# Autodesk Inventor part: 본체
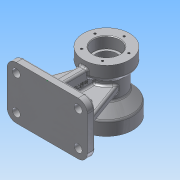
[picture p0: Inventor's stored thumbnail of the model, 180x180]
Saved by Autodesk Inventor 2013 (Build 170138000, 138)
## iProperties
Created: 2015-08
Part Number: 본체
Material: 알루미늄 6061
Document SubType Name: Modeling
Designer: WINDOWS7
Density: 2.71 g/cm^3
Mass: 1062.91 g
Surface Area: 749.728 cm^2
Volume: 392.217 cm^3
Author: WINDOWS7
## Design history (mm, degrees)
sketch "스케치1"
  geometry: 1 further point
sketch "스케치2"
  geometry: C1 r 26 at (0, 90); 1 further point
  constraints: 1 centre point, 1 vertical alignment
  dimensions: "d0" = 52 diameter of C1; "d2" = 90 distance of C1.centre point (0, 0)
extrude "돌출1" new body sketch "스케치2" distance "d3" = 90; taper "d4" = 0 deg
sketch "스케치3"
  geometry: C1 r 26 at (0, 0) reference; C2 r 35 at (0, 0); 1 further point
  constraints: 1 centre point, 1 coincident
  dimensions: "d5" = 70 diameter of C2
extrude "돌출2" join sketch "스케치3" distance "d7" = 20; taper "d8" = 0 deg
sketch "스케치4"
  geometry: C1 r 26 at (0, 0) reference; C2 r 40 at (0, 0); 1 further point
  constraints: 1 centre point, 1 coincident
  dimensions: "d9" = 80 diameter of C2
extrude "돌출3" join sketch "스케치4" distance "d11" = 20; taper "d12" = 0 deg
sketch "스케치5"
  geometry: L1 (125, 0)-(125, -20) reference; L2 (116, -20)-(116, -70) reference; L3 (130, -90)-(130, -70) reference; L4 (55, 0)-(55, -20) reference; L5 (64, -20)-(64, -70) reference; L6 (55, 0)-(125, 0) reference; L7 (64, -20)-(116, -20) reference; L8 (116, -70)-(64, -70) reference; L9 (130, -90)-(50, -90) reference; L10 (90, 0)-(90, -90); L11 (125, -20)-(116, -25.196); L12 (130, -70)-(116, -53.315); L13 (116, -25.196)-(116, -20); L14 (116, -53.315)-(116, -70); 1 further point
  constraints: 10 end point, 2 midpoint, 2 point on line, 1 collinear, 1 parallel
  dimensions: "d13" = 60 deg angle of L2 L11; "d14" = 40 deg angle of L2 L12
revolve "회전1" sketch "스케치5" stored, may be unused: angle "d15" = 90 deg
sketch "스케치6"
  geometry: L1 (61, 0.744)-(-61, 0.744); L2 (-61, 0.744)-(-61, -79.256); L3 (-61, -79.256)-(61, -79.256); L4 (61, -79.256)-(61, 0.744); L5 (26, -25.196)-(26, -53.315) reference; L6 (-26, -25.196)-(-26, -53.315) reference; L7 (-35, 0)-(35, 0) reference; 4 further points
  constraints: 8 end point, 3 midpoint, 2 parallel, 1 horizontal, 1 horizontal alignment, 1 perpendicular, 1 vertical alignment
  dimensions: "d16" = 80 distance of L3.end L1.start; "d18" = 122 distance of L2.end L3.end
extrude "돌출4" join sketch "스케치6" distance "d19" = 12; taper "d20" = 0 deg
node "작업 평면1"
sketch "스케치7"
  geometry: L1 (122, 0)-(0, 0) reference; L2 (0, 0)-(0, 12) reference; L3 (122, 12)-(0, 12) reference; L4 (122, 0)-(122, 12) reference; L5 (10, 12)-(37.488, 87.523); L6 (37.488, 87.523)-(84.512, 87.523); L7 (84.512, 87.523)-(112, 12); 1 further point
  constraints: 6 end point, 2 point on line, 1 perpendicular
  dimensions: "d22" = 10 distance of L3.start L7.end; "d23" = 70 deg angle of L3 L7; "d24" = 10 distance of L2.end L5.start; "d25" = 70 deg angle of L3 L5; "d26" = 47.02406 distance of L5.end L6.end
extrude "돌출5" join sketch "스케치7" stored distance "d27" = 12; taper "d28" = 0 deg
node "작업 평면2"
sketch "스케치8"
  geometry: L1 (80, 12)-(0, 12) reference; L2 (80, 0)-(0, 0) reference; L3 (0, 0)-(0, 12) reference; L4 (80, 12)-(0, 12) reference; L5 (80, 0)-(80, 12) reference; L6 (10, 83.257)-(10, 12); L7 (10, 83.257)-(82.565, 83.257); L8 (82.565, 83.257)-(70, 12); 1 further point
  constraints: 6 end point, 2 perpendicular, 2 point on line, 1 parallel
  dimensions: "d30" = 10 distance of L8.end L1.start; "d31" = 80 deg angle of L1 L8; "d32" = 10 distance of L1.end L6.end; "d33" = 72.5645 distance of L6.start L7.end
extrude "돌출6" join sketch "스케치8" stored distance "d34" = 12; taper "d35" = 0 deg
sketch "스케치9"
  geometry: L1 (79, 42)-(91, 42); L2 (91, 42)-(91, 24); L3 (91, 24)-(79, 24); L4 (79, 24)-(79, 42); A1 r 6 centre (85, 36) between (91, 36) and (79, 36); A2 r 6 centre (85, 30) between (79, 30) and (91, 30); 1 further point
  constraints: 8 end point, 5 point on circle, 4 point on line, 2 centre point, 2 parallel, 2 tangent, 1 equal radius, 1 horizontal, 1 perpendicular, 1 vertical alignment
  dimensions: "d36" = 12 distance of L1.start L1.end; "d38" = 18 distance of L3.end L1.start; "d39" = 12 diameter of A1; "d40" = 24 horizontal distance of point (61, 0) A2.centre; "d41" = 30 vertical distance of point (61, 0) A2.centre
extrude "돌출7" cut sketch "스케치9" distance "d42" = 12; taper "d43" = 0 deg
sketch "스케치10"
  geometry: C1 r 20 at (0, 90); A1 r 35 centre (0, 90) between (0, 125) and (35, 90) reference; 1 further point
  constraints: 1 centre point, 1 coincident
  dimensions: "d44" = 40 diameter of C1
extrude "돌출8" cut sketch "스케치10" distance "d46" = 17; taper "d47" = 0 deg
sketch "스케치11"
  geometry: C1 r 26 at (0, 90); A1 r 40 centre (0, 90) between (0, 130) and (40, 90) reference; 1 further point
  constraints: 1 centre point, 1 coincident
  dimensions: "d48" = 52 diameter of C1
extrude "돌출9" cut sketch "스케치11" distance "d50" = 20; taper "d51" = 0 deg
sketch "스케치12"
  geometry: L1 (6, -39.547)-(6, -25.298) reference; L2 (-6, -25.298)-(-6, -39.547) reference; C1 r 19 at (0, 0); A1 r 26 centre (0, 0) between (6, -25.298) and (-6, -25.298) reference; A2 r 40 centre (0, 0) between (6, -39.547) and (-6, -39.547) reference; 1 further point
  constraints: 1 centre point, 1 coincident
  dimensions: "d52" = 38 diameter of C1
extrude "돌출10" cut sketch "스케치12" distance "d54" = 3; taper "d55" = 0 deg
sketch "스케치13"
  geometry: C1 r 16 at (0, 0); A1 r 35 centre (0, 0) between (6, -34.482) and (-6, -34.482) reference; 1 further point
  constraints: 1 centre point, 1 coincident
  dimensions: "d56" = 32 diameter of C1
extrude "돌출11" cut sketch "스케치13" stored distance "d58" = 3; taper "d59" = 0 deg
sketch "스케치14"
  geometry: A1 r 40 centre (0, 90) between (0, 130) and (40, 90) reference; 3 further points
  constraints: 2 vertical alignment, 1 coincident, 2 other
  dimensions: "d60" = 33 distance of A1.centre point (0, 123)
hole "구멍1" sketch "스케치14" at (0, 123) diameter "d61" = 3.242; stored, may be unused: countersink angle "d65" = 90 deg, drill point angle "d67" = 118 deg; dims "d62" = 10, "d63" = 4, "d64" = 2, "d66" = 13
sketch "스케치15" dims "d71" = 54
  geometry: A1 r 35 centre (0, 90) between (0, 125) and (35, 90) reference; 3 further points
  constraints: 2 vertical alignment, 1 coincident, 2 other
hole "구멍2" sketch "스케치15" at (0, 117) diameter "d73" = 3.242; stored, may be unused: countersink angle "d77" = 90 deg, drill point angle "d79" = 118 deg; dims "d74" = 10, "d75" = 4, "d76" = 2, "d78" = 13
sketch "스케치16"
  geometry: L1 (-61, -0.744)-(61, -0.744) reference; L2 (-61, 79.256)-(-61, -0.744) reference; L3 (61, 79.256)-(-61, 79.256) reference; L4 (61, -0.744)-(61, 79.256) reference; C1 r 6 at (-47, 65.256); C2 r 6 at (-47, 13.256); C3 r 6 at (47, 13.256); C4 r 6 at (47, 65.256); 1 further point
  constraints: 4 centre point, 3 equal radius, 2 horizontal alignment, 2 vertical alignment
  dimensions: "d83" = 12 diameter of C1; "d85" = 94 distance of C4.centre C1.centre; "d86" = 14 distance from line of L2 C1.centre; "d87" = 14 distance from line of L3 C1.centre; "d88" = 52 distance of C2.centre C1.centre
extrude "돌출12" cut sketch "스케치16" distance "d89" = 12; taper "d90" = 0 deg
sketch "스케치17"
  geometry: L1 (0, 0)-(80, 0) reference; L2 (80, 0)-(80, 12) reference; L3 (0, 12)-(80, 12) reference; L4 (0, 0)-(0, 12) reference; L5 (34, 64.702)-(34, 12) reference; L6 (25.94, 64.702)-(34, 64.702) reference; L7 (10, 55.518)-(20.744, 55.518) reference; L8 (10, 55.518)-(10, 12) reference; L9 (34, 12)-(10, 12) reference; 2 further points
  constraints: 2 other
  dimensions: "d91" = 16 distance from line of point (26, 36) L8; "d92" = 24 distance from line of point (26, 36) L3
feature "엠보싱1" sketch "스케치17" dims "d93" = 0.5, "d94" = 0
fillet "모깎기1" dims "d95" = 14
fillet "모깎기2" dims "d96" = 3
fillet "모깎기3" dims "d97" = 3
fillet "모깎기4" dims "d98" = 3
fillet "모깎기5" dims "d99" = 5
chamfer "모따기1" distance "d100" = 1; stored, may be unused: second distance "d101" = 2, angle "d102" = 45 deg
fillet "모깎기6" dims "d103" = 0.3
fillet "모깎기7" dims "d104" = 0.3
fillet "모깎기8" dims "d105" = 3
fillet "모깎기9" dims "d106" = 3
node "솔리드1"
mirror "대칭1"
pattern_circular "원형 패턴1" dims angle "d69" = 360 deg
pattern_circular "원형 패턴2" dims angle "d81" = 360 deg
node "투영된 루프1"
node "투영된 루프2"
node "투영된 루프3"
node "투영된 루프4"
node "투영된 루프5"
node "투영된 루프6"
other parameters: "d29" = -61
